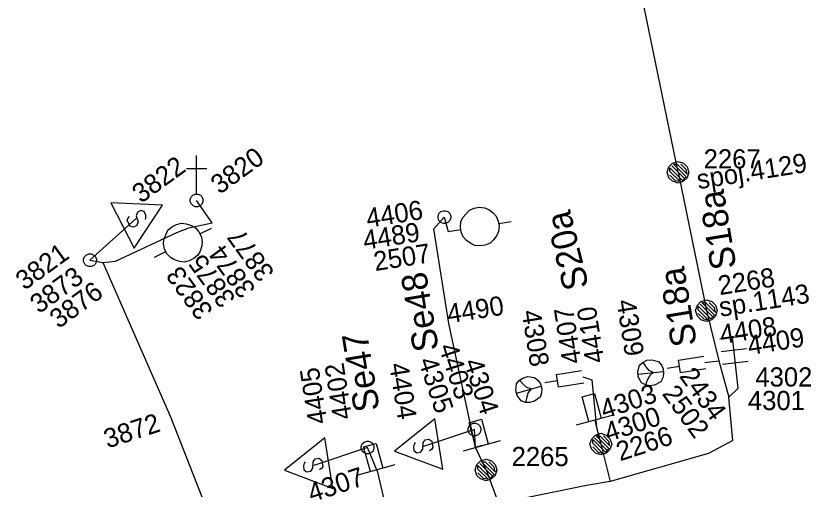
# Model space of a CAD drawing. Extents: x -535557 to -534097, y -1142175 to -1136716.
# Drawn here: x -534937.78 to -534906.68, y -1139069.17 to -1139050.66 of the extents above; entities that cross this region are included whole.
import ezdxf

# ---------------------------------------------------------------- set-up
doc = ezdxf.new("R2010")
doc.units = 0
doc.layers.add('Default', color=7, linetype='Continuous')
doc.layers.add('SS_SZDC', color=7, linetype='Continuous')

# ---------------------------------------------------------------- blocks, each defined once
blk = doc.blocks.new('POINT_DISPLAY')
at = {"layer": 'Default'}
blk.add_line((0, 0), (0, 0), dxfattribs=at)

msp = doc.modelspace()

# ---------------------------------------------------------------- linework, layer by layer
at = {"layer": 'SS_SZDC'}
for p, q in [((-534911.88, -1139056.78), (-534913.409, -1139049.35)), ((-534930.71, -1139057.629), (-534930.71, -1139056.129)), ((-534912.304, -1139056.78), (-534912.233, -1139056.567)), ((-534912.233, -1139056.567), (-534912.092, -1139056.426)), ((-534912.198, -1139056.744), (-534912.198, -1139056.603)), ((-534912.198, -1139056.603), (-534911.703, -1139057.098)), ((-534911.632, -1139057.027), (-534912.127, -1139056.532)), ((-534912.092, -1139056.426), (-534911.88, -1139056.355)), ((-534911.561, -1139056.956), (-534912.056, -1139056.461)), ((-534912.056, -1139056.461), (-534911.915, -1139056.461)), ((-534911.915, -1139056.461), (-534911.526, -1139056.85)), ((-534911.88, -1139056.355), (-534911.667, -1139056.426)), ((-534911.561, -1139056.673), (-534911.773, -1139056.461)), ((-534911.667, -1139056.426), (-534911.526, -1139056.567)), ((-534911.526, -1139056.567), (-534911.455, -1139056.78)), ((-534931.11, -1139056.629), (-534930.31, -1139056.629)), ((-534912.233, -1139056.992), (-534912.304, -1139056.78)), ((-534911.809, -1139057.133), (-534912.198, -1139056.744)), ((-534912.198, -1139056.886), (-534911.986, -1139057.098)), ((-534911.88, -1139056.78), (-534910.77, -1139062.19)), ((-534911.526, -1139056.85), (-534911.561, -1139056.673)), ((-534911.455, -1139056.78), (-534911.526, -1139056.992)), ((-534912.092, -1139057.133), (-534912.233, -1139056.992)), ((-534911.88, -1139057.204), (-534912.092, -1139057.133)), ((-534911.986, -1139057.098), (-534911.809, -1139057.133)), ((-534911.667, -1139057.133), (-534911.88, -1139057.204)), ((-534911.703, -1139057.098), (-534911.561, -1139056.956)), ((-534911.526, -1139056.992), (-534911.667, -1139057.133)), ((-534930.96, -1139057.829), (-534930.91, -1139057.729)), ((-534930.96, -1139057.929), (-534930.96, -1139057.829)), ((-534930.91, -1139057.729), (-534930.86, -1139057.679)), ((-534930.86, -1139057.679), (-534930.76, -1139057.629)), ((-534930.76, -1139057.629), (-534930.66, -1139057.629)), ((-534930.66, -1139057.629), (-534930.56, -1139057.679)), ((-534930.56, -1139057.679), (-534930.51, -1139057.729)), ((-534930.51, -1139057.729), (-534930.46, -1139057.829)), ((-534930.46, -1139057.829), (-534930.46, -1139057.929)), ((-534934.058, -1139057.971), (-534933.15, -1139059.753)), ((-534932.045, -1139058.067), (-534934.058, -1139057.971)), ((-534933.15, -1139059.753), (-534932.045, -1139058.067)), ((-534930.91, -1139058.029), (-534930.96, -1139057.929)), ((-534930.86, -1139058.079), (-534930.91, -1139058.029)), ((-534930.76, -1139058.129), (-534930.86, -1139058.079)), ((-534930.66, -1139058.129), (-534930.76, -1139058.129)), ((-534930.1, -1139058.76), (-534930.71, -1139057.879)), ((-534930.56, -1139058.079), (-534930.66, -1139058.129)), ((-534930.51, -1139058.029), (-534930.56, -1139058.079)), ((-534930.46, -1139057.929), (-534930.51, -1139058.029)), ((-534919.851, -1139058.179), (-534919.653, -1139058.148)), ((-534919.653, -1139058.148), (-534919.448, -1139058.166)), ((-534919.448, -1139058.166), (-534919.284, -1139058.241)), ((-534933.027, -1139058.343), (-534933.07, -1139058.478)), ((-534933.07, -1139058.478), (-534933.001, -1139058.723)), ((-534932.893, -1139058.275), (-534933.027, -1139058.343)), ((-534932.758, -1139058.319), (-534932.893, -1139058.275)), ((-534932.69, -1139058.452), (-534932.758, -1139058.319)), ((-534932.69, -1139058.564), (-534932.69, -1139058.452)), ((-534921.267, -1139058.494), (-534921.232, -1139058.388)), ((-534921.232, -1139058.388), (-534921.161, -1139058.317)), ((-534921.161, -1139058.317), (-534921.055, -1139058.282)), ((-534921.055, -1139058.282), (-534920.984, -1139058.282)), ((-534920.984, -1139058.282), (-534920.878, -1139058.317)), ((-534920.878, -1139058.317), (-534920.807, -1139058.388)), ((-534920.807, -1139058.388), (-534920.772, -1139058.494)), ((-534920.298, -1139058.553), (-534920.041, -1139058.26)), ((-534920.041, -1139058.26), (-534919.851, -1139058.179)), ((-534919.284, -1139058.241), (-534919.113, -1139058.366)), ((-534919.113, -1139058.366), (-534918.99, -1139058.498)), ((-534933.069, -1139058.59), (-534934.88, -1139060.219)), ((-534933.427, -1139058.659), (-534933.405, -1139058.592)), ((-534933.313, -1139058.882), (-534933.427, -1139058.659)), ((-534933.405, -1139058.592), (-534933.338, -1139058.502)), ((-534933.001, -1139058.723), (-534933.045, -1139058.858)), ((-534932.711, -1139058.632), (-534932.69, -1139058.564)), ((-534931.497, -1139058.818), (-534931.296, -1139058.772)), ((-534931.296, -1139058.772), (-534931.117, -1139058.793)), ((-534931.117, -1139058.793), (-534930.915, -1139058.859)), ((-534931.01, -1139058.95), (-534930.1, -1139058.76)), ((-534921.43, -1139058.989), (-534921.02, -1139058.53)), ((-534921.267, -1139058.565), (-534921.267, -1139058.494)), ((-534921.232, -1139058.671), (-534921.267, -1139058.565)), ((-534921.161, -1139058.742), (-534921.232, -1139058.671)), ((-534921.055, -1139058.777), (-534921.161, -1139058.742)), ((-534920.984, -1139058.777), (-534921.055, -1139058.777)), ((-534921.02, -1139058.53), (-534920.869, -1139059.1)), ((-534920.878, -1139058.742), (-534920.984, -1139058.777)), ((-534920.807, -1139058.671), (-534920.878, -1139058.742)), ((-534920.772, -1139058.565), (-534920.807, -1139058.671)), ((-534920.772, -1139058.494), (-534920.772, -1139058.565)), ((-534920.391, -1139058.923), (-534920.373, -1139058.717)), ((-534920.373, -1139058.717), (-534920.298, -1139058.553)), ((-534918.99, -1139058.498), (-534918.91, -1139058.688)), ((-534918.91, -1139058.688), (-534918.878, -1139058.885)), ((-534918.894, -1139058.787), (-534918.4, -1139058.708)), ((-534933.179, -1139058.926), (-534933.313, -1139058.882)), ((-534933.045, -1139058.858), (-534933.179, -1139058.926)), ((-534931.985, -1139059.403), (-534931.831, -1139059.045)), ((-534931.831, -1139059.045), (-534931.675, -1139058.909)), ((-534931.675, -1139058.909), (-534931.497, -1139058.818)), ((-534931.479, -1139059.129), (-534931.01, -1139058.95)), ((-534930.915, -1139058.859), (-534930.758, -1139058.947)), ((-534930.758, -1139058.947), (-534930.623, -1139059.102)), ((-534930.623, -1139059.102), (-534930.532, -1139059.281)), ((-534930.577, -1139059.192), (-534930.132, -1139058.965)), ((-534920.85, -1139062.69), (-534921.43, -1139058.989)), ((-534920.869, -1139059.1), (-534920.376, -1139059.021)), ((-534920.376, -1139059.021), (-534920.391, -1139058.923)), ((-534920.36, -1139059.12), (-534920.376, -1139059.021)), ((-534918.897, -1139059.091), (-534918.972, -1139059.255)), ((-534918.878, -1139058.885), (-534918.897, -1139059.091)), ((-534933.88, -1139060.26), (-534931.479, -1139059.129)), ((-534932.006, -1139059.583), (-534931.985, -1139059.403)), ((-534930.532, -1139059.281), (-534930.486, -1139059.482)), ((-534920.279, -1139059.31), (-534920.36, -1139059.12)), ((-534920.157, -1139059.442), (-534920.279, -1139059.31)), ((-534918.972, -1139059.255), (-534919.097, -1139059.426)), ((-534931.959, -1139059.783), (-534932.006, -1139059.583)), ((-534930.507, -1139059.661), (-534930.572, -1139059.862)), ((-534930.486, -1139059.482), (-534930.507, -1139059.661)), ((-534919.985, -1139059.567), (-534920.157, -1139059.442)), ((-534919.822, -1139059.642), (-534919.985, -1139059.567)), ((-534919.616, -1139059.66), (-534919.822, -1139059.642)), ((-534919.419, -1139059.629), (-534919.616, -1139059.66)), ((-534919.229, -1139059.548), (-534919.419, -1139059.629)), ((-534919.097, -1139059.426), (-534919.229, -1139059.548)), ((-534935.08, -1139060.069), (-534935.03, -1139060.019)), ((-534935.03, -1139060.019), (-534934.93, -1139059.969)), ((-534934.93, -1139059.969), (-534934.83, -1139059.969)), ((-534934.83, -1139059.969), (-534934.73, -1139060.019)), ((-534934.73, -1139060.019), (-534934.68, -1139060.069)), ((-534932.359, -1139060.1), (-534931.914, -1139059.873)), ((-534931.914, -1139059.873), (-534931.959, -1139059.783)), ((-534931.869, -1139059.962), (-534931.914, -1139059.873)), ((-534931.733, -1139060.117), (-534931.869, -1139059.962)), ((-534930.661, -1139060.02), (-534930.816, -1139060.155)), ((-534930.572, -1139059.862), (-534930.661, -1139060.02)), ((-534935.13, -1139060.169), (-534935.08, -1139060.069)), ((-534935.13, -1139060.269), (-534935.13, -1139060.169)), ((-534935.08, -1139060.369), (-534935.13, -1139060.269)), ((-534934.88, -1139060.219), (-534934.38, -1139060.309)), ((-534934.68, -1139060.069), (-534934.63, -1139060.169)), ((-534934.63, -1139060.269), (-534934.68, -1139060.369)), ((-534934.63, -1139060.169), (-534934.63, -1139060.269)), ((-534934.38, -1139060.309), (-534933.88, -1139060.26)), ((-534934.38, -1139060.309), (-534931.729, -1139066.34)), ((-534931.576, -1139060.205), (-534931.733, -1139060.117)), ((-534931.374, -1139060.271), (-534931.576, -1139060.205)), ((-534931.195, -1139060.292), (-534931.374, -1139060.271)), ((-534930.994, -1139060.246), (-534931.195, -1139060.292)), ((-534930.816, -1139060.155), (-534930.994, -1139060.246)), ((-534935.03, -1139060.419), (-534935.08, -1139060.369)), ((-534934.93, -1139060.469), (-534935.03, -1139060.419)), ((-534934.83, -1139060.469), (-534934.93, -1139060.469)), ((-534934.73, -1139060.419), (-534934.83, -1139060.469)), ((-534934.68, -1139060.369), (-534934.73, -1139060.419)), ((-534911.123, -1139061.977), (-534910.982, -1139061.836)), ((-534910.982, -1139061.836), (-534910.77, -1139061.765)), ((-534910.451, -1139062.366), (-534910.946, -1139061.871)), ((-534910.946, -1139061.871), (-534910.805, -1139061.871)), ((-534910.805, -1139061.871), (-534910.416, -1139062.26)), ((-534910.77, -1139061.765), (-534910.557, -1139061.836)), ((-534910.451, -1139062.083), (-534910.663, -1139061.871)), ((-534910.557, -1139061.836), (-534910.416, -1139061.977)), ((-534911.194, -1139062.19), (-534911.123, -1139061.977)), ((-534911.123, -1139062.402), (-534911.194, -1139062.19)), ((-534911.088, -1139062.154), (-534911.088, -1139062.013)), ((-534911.088, -1139062.013), (-534910.593, -1139062.508)), ((-534910.699, -1139062.543), (-534911.088, -1139062.154)), ((-534910.522, -1139062.437), (-534911.017, -1139061.942)), ((-534910.77, -1139062.19), (-534910.289, -1139064.149)), ((-534910.416, -1139062.26), (-534910.451, -1139062.083)), ((-534910.416, -1139061.977), (-534910.345, -1139062.19)), ((-534910.345, -1139062.19), (-534910.416, -1139062.402)), ((-534910.982, -1139062.543), (-534911.123, -1139062.402)), ((-534911.088, -1139062.296), (-534910.876, -1139062.508)), ((-534910.876, -1139062.508), (-534910.699, -1139062.543)), ((-534910.593, -1139062.508), (-534910.451, -1139062.366)), ((-534910.416, -1139062.402), (-534910.557, -1139062.543)), ((-534919.8, -1139067.54), (-534920.85, -1139062.69)), ((-534910.77, -1139062.614), (-534910.982, -1139062.543)), ((-534910.557, -1139062.543), (-534910.77, -1139062.614)), ((-534910.246, -1139063.286), (-534909.252, -1139063.177)), ((-534909.529, -1139065.219), (-534909.749, -1139063.232)), ((-534910.191, -1139063.783), (-534909.197, -1139063.674)), ((-534911.856, -1139064.129), (-534910.869, -1139063.973)), ((-534913.457, -1139064.575), (-534913.385, -1139064.316)), ((-534913.385, -1139064.316), (-534913.247, -1139064.2)), ((-534913.247, -1139064.2), (-534913.104, -1139064.133)), ((-534913.126, -1139064.387), (-534913.247, -1139064.2)), ((-534913.01, -1139064.526), (-534913.126, -1139064.387)), ((-534913.104, -1139064.133), (-534912.905, -1139064.112)), ((-534912.905, -1139064.112), (-534912.646, -1139064.184)), ((-534912.646, -1139064.184), (-534912.53, -1139064.322)), ((-534912.53, -1139064.322), (-534912.463, -1139064.465)), ((-534911.817, -1139064.376), (-534912.311, -1139064.454)), ((-534911.778, -1139064.623), (-534911.856, -1139064.129)), ((-534910.829, -1139064.219), (-534910.289, -1139064.149)), ((-534910.289, -1139064.149), (-534909.899, -1139065.569)), ((-534910.136, -1139064.28), (-534909.142, -1139064.171)), ((-534916.636, -1139064.689), (-534915.649, -1139064.533)), ((-534916.558, -1139065.183), (-534916.636, -1139064.689)), ((-534913.436, -1139064.774), (-534913.457, -1139064.575)), ((-534913.446, -1139064.674), (-534912.453, -1139064.565)), ((-534912.85, -1139064.609), (-534913.01, -1139064.526)), ((-534912.85, -1139064.609), (-534912.988, -1139064.724)), ((-534912.442, -1139064.664), (-534912.475, -1139064.819)), ((-534912.463, -1139064.465), (-534912.442, -1139064.664)), ((-534910.79, -1139064.466), (-534911.778, -1139064.623)), ((-534918.198, -1139065.047), (-534918.079, -1139064.911)), ((-534918.079, -1139064.911), (-534917.948, -1139064.824)), ((-534917.93, -1139065.078), (-534918.079, -1139064.911)), ((-534917.948, -1139064.824), (-534917.755, -1139064.771)), ((-534917.755, -1139064.771), (-534917.487, -1139064.801)), ((-534917.487, -1139064.801), (-534917.351, -1139064.92)), ((-534917.351, -1139064.92), (-534917.264, -1139065.051)), ((-534916.597, -1139064.936), (-534917.091, -1139065.014)), ((-534915.609, -1139064.78), (-534915.25, -1139064.899)), ((-534915.25, -1139064.899), (-534915.069, -1139066.76)), ((-534913.309, -1139065.011), (-534913.436, -1139064.774)), ((-534913.149, -1139065.094), (-534913.309, -1139065.011)), ((-534913.071, -1139064.884), (-534913.149, -1139065.094)), ((-534912.988, -1139064.724), (-534913.071, -1139064.884)), ((-534912.558, -1139064.979), (-534912.795, -1139065.106)), ((-534912.475, -1139064.819), (-534912.558, -1139064.979)), ((-534918.228, -1139065.315), (-534918.198, -1139065.047)), ((-534918.175, -1139065.508), (-534918.228, -1139065.315)), ((-534918.202, -1139065.411), (-534917.237, -1139065.148)), ((-534917.794, -1139065.196), (-534917.93, -1139065.078)), ((-534917.623, -1139065.253), (-534917.794, -1139065.196)), ((-534917.623, -1139065.253), (-534917.741, -1139065.389)), ((-534917.264, -1139065.051), (-534917.211, -1139065.244)), ((-534917.211, -1139065.244), (-534917.219, -1139065.402)), ((-534915.57, -1139065.026), (-534916.558, -1139065.183)), ((-534912.994, -1139065.127), (-534913.149, -1139065.094)), ((-534912.795, -1139065.106), (-534912.994, -1139065.127)), ((-534909.899, -1139065.569), (-534909.529, -1139065.219)), ((-534918.013, -1139065.723), (-534918.175, -1139065.508)), ((-534917.798, -1139065.56), (-534917.842, -1139065.78)), ((-534917.741, -1139065.389), (-534917.798, -1139065.56)), ((-534917.276, -1139065.573), (-534917.491, -1139065.735)), ((-534917.219, -1139065.402), (-534917.276, -1139065.573)), ((-534915.635, -1139065.561), (-534915.152, -1139065.429)), ((-534915.371, -1139066.525), (-534915.635, -1139065.561)), ((-534915.152, -1139065.429), (-534914.888, -1139066.394)), ((-534909.739, -1139067.27), (-534909.899, -1139065.569)), ((-534917.842, -1139065.78), (-534918.013, -1139065.723)), ((-534917.684, -1139065.788), (-534917.842, -1139065.78)), ((-534917.491, -1139065.735), (-534917.684, -1139065.788)), ((-534931.729, -1139066.34), (-534929.05, -1139073.18)), ((-534921.393, -1139066.418), (-534922.965, -1139067.679)), ((-534921.08, -1139068.393), (-534921.393, -1139066.418)), ((-534920.055, -1139066.571), (-534919.572, -1139066.439)), ((-534919.791, -1139067.535), (-534920.055, -1139066.571)), ((-534919.572, -1139066.439), (-534919.308, -1139067.404)), ((-534915.853, -1139066.657), (-534914.406, -1139066.262)), ((-534915.13, -1139066.459), (-534915.069, -1139066.76)), ((-534919.84, -1139066.84), (-534921.829, -1139067.5)), ((-534920.087, -1139066.804), (-534920.052, -1139066.698)), ((-534920.087, -1139066.875), (-534920.087, -1139066.804)), ((-534920.052, -1139066.981), (-534920.087, -1139066.875)), ((-534920.052, -1139066.698), (-534919.981, -1139066.627)), ((-534919.981, -1139066.627), (-534919.875, -1139066.592)), ((-534919.875, -1139066.592), (-534919.804, -1139066.592)), ((-534919.8, -1139067.54), (-534919.84, -1139066.84)), ((-534919.804, -1139066.592), (-534919.698, -1139066.627)), ((-534919.698, -1139066.627), (-534919.627, -1139066.698)), ((-534919.627, -1139066.698), (-534919.592, -1139066.804)), ((-534919.592, -1139066.875), (-534919.627, -1139066.981)), ((-534919.592, -1139066.804), (-534919.592, -1139066.875)), ((-534915.069, -1139066.76), (-534914.9, -1139067.41)), ((-534925.693, -1139067.168), (-534927.265, -1139068.429)), ((-534925.38, -1139069.143), (-534925.693, -1139067.168)), ((-534919.981, -1139067.052), (-534920.052, -1139066.981)), ((-534919.875, -1139067.087), (-534919.981, -1139067.052)), ((-534919.804, -1139067.087), (-534919.875, -1139067.087)), ((-534919.698, -1139067.052), (-534919.804, -1139067.087)), ((-534919.627, -1139066.981), (-534919.698, -1139067.052)), ((-534915.253, -1139067.197), (-534915.112, -1139067.056)), ((-534914.652, -1139067.657), (-534915.147, -1139067.162)), ((-534915.112, -1139067.056), (-534914.9, -1139066.985)), ((-534914.581, -1139067.586), (-534915.076, -1139067.091)), ((-534915.076, -1139067.091), (-534914.935, -1139067.091)), ((-534914.935, -1139067.091), (-534914.546, -1139067.48)), ((-534914.9, -1139066.985), (-534914.687, -1139067.056)), ((-534914.581, -1139067.303), (-534914.793, -1139067.091)), ((-534914.687, -1139067.056), (-534914.546, -1139067.197)), ((-534924.267, -1139067.504), (-534924.232, -1139067.398)), ((-534924.267, -1139067.575), (-534924.267, -1139067.504)), ((-534924.232, -1139067.398), (-534924.161, -1139067.327)), ((-534924.175, -1139067.511), (-534923.692, -1139067.379)), ((-534924.161, -1139067.327), (-534924.055, -1139067.292)), ((-534924.055, -1139067.292), (-534923.984, -1139067.292)), ((-534923.984, -1139067.292), (-534923.878, -1139067.327)), ((-534923.878, -1139067.327), (-534923.807, -1139067.398)), ((-534923.807, -1139067.398), (-534923.772, -1139067.504)), ((-534923.772, -1139067.504), (-534923.772, -1139067.575)), ((-534923.692, -1139067.379), (-534923.428, -1139068.344)), ((-534922.199, -1139067.406), (-534922.232, -1139067.513)), ((-534922.157, -1139067.349), (-534922.199, -1139067.406)), ((-534921.863, -1139067.606), (-534921.853, -1139067.351)), ((-534921.853, -1139067.351), (-534921.77, -1139067.237)), ((-534921.77, -1139067.237), (-534921.622, -1139067.213)), ((-534921.622, -1139067.213), (-534921.507, -1139067.297)), ((-534921.507, -1139067.297), (-534921.468, -1139067.544)), ((-534920.273, -1139067.667), (-534918.826, -1139067.272)), ((-534919.55, -1139067.469), (-534919.8, -1139067.54)), ((-534915.324, -1139067.41), (-534915.253, -1139067.197)), ((-534915.253, -1139067.622), (-534915.324, -1139067.41)), ((-534915.218, -1139067.374), (-534915.218, -1139067.233)), ((-534915.218, -1139067.233), (-534914.723, -1139067.728)), ((-534914.829, -1139067.763), (-534915.218, -1139067.374)), ((-534914.9, -1139067.41), (-534914.529, -1139068.87)), ((-534914.546, -1139067.48), (-534914.581, -1139067.303)), ((-534914.546, -1139067.197), (-534914.475, -1139067.41)), ((-534914.475, -1139067.41), (-534914.546, -1139067.622)), ((-534909.739, -1139067.27), (-534910.689, -1139067.78)), ((-534924.02, -1139067.54), (-534926.13, -1139068.25)), ((-534924.232, -1139067.681), (-534924.267, -1139067.575)), ((-534924.161, -1139067.752), (-534924.232, -1139067.681)), ((-534923.911, -1139068.475), (-534924.175, -1139067.511)), ((-534924.055, -1139067.787), (-534924.161, -1139067.752)), ((-534923.984, -1139067.787), (-534924.055, -1139067.787)), ((-534923.649, -1139068.45), (-534924.02, -1139067.54)), ((-534923.878, -1139067.752), (-534923.984, -1139067.787)), ((-534923.807, -1139067.681), (-534923.878, -1139067.752)), ((-534923.772, -1139067.575), (-534923.807, -1139067.681)), ((-534922.965, -1139067.679), (-534921.08, -1139068.393)), ((-534922.232, -1139067.513), (-534922.209, -1139067.661)), ((-534922.209, -1139067.661), (-534922.095, -1139067.744)), ((-534922.095, -1139067.744), (-534921.946, -1139067.721)), ((-534921.946, -1139067.721), (-534921.863, -1139067.606)), ((-534921.51, -1139067.601), (-534921.601, -1139067.666)), ((-534921.468, -1139067.544), (-534921.51, -1139067.601)), ((-534919.39, -1139068.42), (-534919.8, -1139067.54)), ((-534915.112, -1139067.763), (-534915.253, -1139067.622)), ((-534915.218, -1139067.516), (-534915.006, -1139067.728)), ((-534914.9, -1139067.834), (-534915.112, -1139067.763)), ((-534915.006, -1139067.728), (-534914.829, -1139067.763)), ((-534914.687, -1139067.763), (-534914.9, -1139067.834)), ((-534914.723, -1139067.728), (-534914.581, -1139067.586)), ((-534914.546, -1139067.622), (-534914.687, -1139067.763)), ((-534910.689, -1139067.78), (-534914.529, -1139068.87)), ((-534926.457, -1139068.099), (-534926.499, -1139068.156)), ((-534926.163, -1139068.356), (-534926.153, -1139068.101)), ((-534926.153, -1139068.101), (-534926.07, -1139067.987)), ((-534926.07, -1139067.987), (-534925.922, -1139067.963)), ((-534925.922, -1139067.963), (-534925.807, -1139068.047)), ((-534925.807, -1139068.047), (-534925.768, -1139068.294)), ((-534919.743, -1139068.207), (-534919.602, -1139068.066)), ((-534919.602, -1139068.066), (-534919.39, -1139067.995)), ((-534919.071, -1139068.596), (-534919.566, -1139068.101)), ((-534919.566, -1139068.101), (-534919.425, -1139068.101)), ((-534919.425, -1139068.101), (-534919.036, -1139068.49)), ((-534919.39, -1139067.995), (-534919.177, -1139068.066)), ((-534919.071, -1139068.313), (-534919.283, -1139068.101)), ((-534919.177, -1139068.066), (-534919.036, -1139068.207)), ((-534927.265, -1139068.429), (-534925.38, -1139069.143)), ((-534926.499, -1139068.156), (-534926.532, -1139068.263)), ((-534926.532, -1139068.263), (-534926.509, -1139068.411)), ((-534926.509, -1139068.411), (-534926.395, -1139068.494)), ((-534926.246, -1139068.471), (-534926.163, -1139068.356)), ((-534925.81, -1139068.351), (-534925.901, -1139068.416)), ((-534925.768, -1139068.294), (-534925.81, -1139068.351)), ((-534924.393, -1139068.607), (-534922.946, -1139068.212)), ((-534923.67, -1139068.409), (-534923.649, -1139068.45)), ((-534919.814, -1139068.42), (-534919.743, -1139068.207)), ((-534919.743, -1139068.632), (-534919.814, -1139068.42)), ((-534919.708, -1139068.384), (-534919.708, -1139068.243)), ((-534919.708, -1139068.243), (-534919.213, -1139068.738)), ((-534919.319, -1139068.773), (-534919.708, -1139068.384)), ((-534919.142, -1139068.667), (-534919.637, -1139068.172)), ((-534919.39, -1139068.42), (-534918.899, -1139069.729)), ((-534919.036, -1139068.49), (-534919.071, -1139068.313)), ((-534919.036, -1139068.207), (-534918.965, -1139068.42)), ((-534918.965, -1139068.42), (-534919.036, -1139068.632)), ((-534926.395, -1139068.494), (-534926.246, -1139068.471)), ((-534923.649, -1139068.45), (-534923.109, -1139070.77)), ((-534919.602, -1139068.773), (-534919.743, -1139068.632)), ((-534919.708, -1139068.526), (-534919.496, -1139068.738)), ((-534919.496, -1139068.738), (-534919.319, -1139068.773)), ((-534919.213, -1139068.738), (-534919.071, -1139068.596)), ((-534919.036, -1139068.632), (-534919.177, -1139068.773)), ((-534919.39, -1139068.844), (-534919.602, -1139068.773)), ((-534919.177, -1139068.773), (-534919.39, -1139068.844)), ((-534915.46, -1139069.03), (-534918.899, -1139069.729)), ((-534914.529, -1139068.87), (-534915.46, -1139069.03))]:
    msp.add_line(p, q, dxfattribs=at)

# ---------------------------------------------------------------- block references
for p in [(-534911.88, -1139056.78), (-534930.71, -1139057.879), (-534930.71, -1139057.879), (-534933.069, -1139058.59), (-534930.1, -1139058.76), (-534921.02, -1139058.53), (-534921.02, -1139058.53), (-534931.01, -1139058.95), (-534921.43, -1139058.989), (-534920.869, -1139059.1), (-534931.479, -1139059.129), (-534934.88, -1139060.219), (-534934.88, -1139060.219), (-534934.38, -1139060.309), (-534933.88, -1139060.26), (-534932.359, -1139060.1), (-534910.77, -1139062.19), (-534920.85, -1139062.69), (-534910.829, -1139064.219), (-534910.289, -1139064.149), (-534912.949, -1139064.62), (-534915.609, -1139064.78), (-534915.25, -1139064.899), (-534917.72, -1139065.28), (-534909.529, -1139065.219), (-534909.899, -1139065.569), (-534931.729, -1139066.34), (-534915.13, -1139066.459), (-534919.84, -1139066.84), (-534919.84, -1139066.84), (-534915.069, -1139066.76), (-534921.829, -1139067.5), (-534919.55, -1139067.469), (-534914.9, -1139067.41), (-534909.739, -1139067.27), (-534924.02, -1139067.54), (-534924.02, -1139067.54), (-534919.8, -1139067.54), (-534910.689, -1139067.78), (-534926.13, -1139068.25), (-534923.67, -1139068.409), (-534919.39, -1139068.42), (-534923.649, -1139068.45), (-534915.46, -1139069.03), (-534914.529, -1139068.87)]:
    msp.add_blockref('POINT_DISPLAY', p, dxfattribs=at)

# ---------------------------------------------------------------- texts
for s, height, rotation, p in [('3820', 0.75, 36, (-534929.807, -1139057.667)), ('3822', 0.75, 36, (-534932.881, -1139058.016)), ('spoj.4129', 0.75, 9, (-534911.085, -1139057.442)), ('S18a', 1, 99.3757, (-534909.592, -1139060.497)), ('4406', 0.75, 9, (-534924.017, -1139058.951)), ('S20a', 1, 103.8757, (-534915.36, -1139061.245)), ('4489', 0.75, 9, (-534924.138, -1139059.816)), ('3877', 0.75, 126, (-534927.632, -1139060.697)), ('3821', 0.75, 36, (-534937.438, -1139061.417)), ('3874', 0.75, 126, (-534928.368, -1139061.342)), ('2507', 0.75, 9, (-534923.724, -1139060.644)), ('3875', 0.75, 126, (-534929.151, -1139061.715)), ('3873', 0.75, 36, (-534936.873, -1139062.334)), ('3823', 0.75, 126, (-534930.033, -1139062.188)), ('S18a', 1, 99.3757, (-534911.137, -1139063.511)), ('2268', 0.75, 9, (-534910.252, -1139061.586)), ('Se48', 1, 99.3757, (-534921.233, -1139063.704)), ('3876', 0.75, 36, (-534936.109, -1139062.916)), ('sp.1143', 0.75, 9, (-534910.217, -1139062.431)), ('4490', 0.75, 9, (-534920.85, -1139062.69)), ('4309', 0.75, 279, (-534914.29, -1139061.812)), ('4308', 0.75, 279, (-534917.999, -1139062.221)), ('4407', 0.75, 99, (-534915.651, -1139064.213)), ('4410', 0.75, 99, (-534914.755, -1139064.184)), ('4408', 0.75, 9, (-534910.183, -1139063.499)), ('4409', 0.75, 9, (-534909.097, -1139063.93)), ('Se47', 1, 99.3757, (-534923.543, -1139066.058)), ('4403', 0.75, 288, (-534921.249, -1139063.603)), ('4402', 0.75, 99, (-534924.62, -1139066.392)), ('4404', 0.75, 279, (-534923.178, -1139064.287)), ('4305', 0.75, 288, (-534922.041, -1139064.147)), ('4304', 0.75, 288, (-534920.267, -1139064.196)), ('4405', 0.75, 99, (-534925.592, -1139066.569)), ('2434', 0.75, 306, (-534911.857, -1139064.755)), ('4303', 0.75, 18, (-534914.768, -1139066.43)), ('2502', 0.75, 306, (-534912.529, -1139065.442)), ('3872', 0.75, 18, (-534934.193, -1139067.585)), ('4300', 0.75, 18, (-534914.613, -1139067.326)), ('2266', 0.75, 18, (-534914.148, -1139068.085)), ('4307', 0.75, 18, (-534926.211, -1139069.692))]:
    msp.add_text(s, height=height, rotation=rotation, dxfattribs=at).set_placement(p)
for s, p in [('2267', (-534910.879, -1139056.629)), ('4302', (-534908.856, -1139065.158)), ('4301', (-534909.148, -1139066.078)), ('2265', (-534918.389, -1139068.269))]:
    msp.add_text(s, height=0.75, dxfattribs=at).set_placement(p)

doc.saveas('drawing.dxf')
